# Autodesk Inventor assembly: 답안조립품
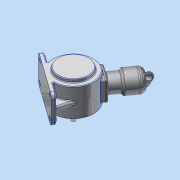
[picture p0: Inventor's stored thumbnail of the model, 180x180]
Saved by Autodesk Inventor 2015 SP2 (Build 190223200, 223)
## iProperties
Created: 2015-06
Part Number: 답안조립품
Document SubType Name: Assembly
Designer: AMC
Author: AMC
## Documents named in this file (15)
- C:\Users\AMC\Desktop\450606V1025\답안조립품.iam
- C:\Users\AMC\Desktop\450606V1025\본체.ipt
- C:\Users\AMC\Desktop\450606V1025\베어링 6204.ipt
- C:\Users\AMC\Desktop\450606V1025\메인커버.ipt
- C:\Users\AMC\Desktop\450606V1025\M4x0.7.ipt
- C:\Users\AMC\Desktop\450606V1025\메인 크랭크 축-구동부.ipt
- C:\Users\AMC\Desktop\450606V1025\오일실.ipt
- C:\Users\AMC\Desktop\450606V1025\크랭크 서브축.ipt
- C:\Users\AMC\Desktop\450606V1025\실린더.ipt
- C:\Users\AMC\Desktop\450606V1025\실린더헤드.ipt
- C:\Users\AMC\Desktop\450606V1025\M5x0.8.ipt
- C:\Users\AMC\Desktop\450606V1025\커넥팅 로드.ipt
- C:\Users\AMC\Desktop\450606V1025\베어링 NA 4902.ipt
- C:\Users\AMC\Desktop\450606V1025\피스톤.ipt
- C:\Users\AMC\Desktop\450606V1025\피스톤 핀.ipt
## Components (14 placed, 4 different names)
1. 피스톤:1 — 강체:1
2. 피스톤 핀:1 — 강체:1
3. M4x0.7:1
4. M4x0.7:2
5. M4x0.7:3
6. M4x0.7:4
7. M4x0.7:5
8. M4x0.7:6
9. M4x0.7:7
10. M4x0.7:8
11. M5x0.8:1
12. M5x0.8:2
13. M5x0.8:3
14. M5x0.8:4
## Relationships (1: WeldJoint 1)
- 강체:1 [WeldJoint]: 피스톤:1 ↔ 피스톤 핀:1
